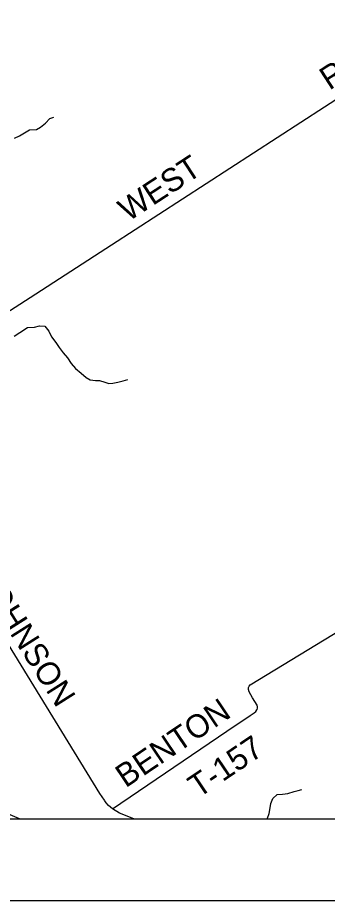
# Model space of a CAD drawing. Extents: x 0 to 34, y 0 to 22.
# Drawn here: x 3.909 to 4.289, y 14 to 15.083 of the extents above; entities that cross this region are included whole.
import ezdxf

# ---------------------------------------------------------------- set-up
doc = ezdxf.new("R2010")
doc.units = 0
for name, color, linetype in [('GM_X_Corporation', 7, 'Continuous'), ('GM_X_County_Road', 7, 'Continuous'), ('GM_X_County_Road_Text', 7, 'Continuous'), ('GM_X_Minor_River', 7, 'Continuous'), ('GM_X_Rail_Line', 7, 'Continuous'), ('GM_X_Township_Road', 7, 'Continuous'), ('GM_X_Township_Road_Text', 7, 'Continuous'), ('SH_Data', 7, 'Continuous')]:
    doc.layers.add(name, color=color, linetype=linetype)

msp = doc.modelspace()

# ---------------------------------------------------------------- linework, layer by layer
at = {"layer": 'GM_X_Corporation'}
msp.add_lwpolyline([(2.8939, 16.1007), (2.8444, 15.5792), (2.791, 14.9974), (2.7825, 14.9057), (2.7612, 14.682), (2.7426, 14.4873), (2.7141, 14.1915), (2.7124, 14.1801), (2.7115, 14.1703), (2.7095, 14.1457), (2.7076, 14.1245), (2.7052, 14.1), (8.9, 14.1)], dxfattribs=at)
at = {"layer": 'GM_X_County_Road'}
for points in [[(3.7386, 14.6201), (3.9241, 14.7398), (4.024, 14.8043), (4.3438, 15.011), (4.352, 15.0164), (4.3575, 15.0207), (4.3594, 15.0236), (4.361, 15.0279), (4.3615, 15.0333), (4.361, 15.0387), (4.3591, 15.0433), (4.3522, 15.0538), (4.306, 15.1259), (4.6205, 15.2578), (4.8635, 15.2772), (5.1173, 15.2978), (5.2791, 15.3117)], [(4.0153, 14.1229), (4.0098, 14.1309), (3.793, 14.4839), (3.787, 14.4942), (3.7866, 14.4951)], [(4.0517, 14.1), (4.0338, 14.1069), (4.0252, 14.1121), (4.0206, 14.1162), (4.0174, 14.1198), (4.0158, 14.1221), (4.0153, 14.1229)]]:
    msp.add_lwpolyline(points, dxfattribs=at)
at = {"layer": 'GM_X_Minor_River'}
for points in [[(3.9236, 14.9455), (3.9318, 14.9459), (3.9369, 14.9487), (3.943, 14.9534), (3.9485, 14.9591), (3.9532, 14.9609)], [(3.9113, 14.938), (3.9236, 14.9455)], [(3.9049, 14.9352), (3.9113, 14.938)], [(3.9044, 14.6923), (3.9114, 14.6967), (3.9209, 14.7029)], [(3.9209, 14.7029), (3.9296, 14.7034), (3.9358, 14.7047), (3.9424, 14.7043), (3.947, 14.6982), (3.9505, 14.6912), (3.9556, 14.6845), (3.9599, 14.6782), (3.9648, 14.6717), (3.9699, 14.6657), (3.9744, 14.6588), (3.98, 14.6527), (3.987, 14.6466), (3.993, 14.6414), (3.998, 14.6388), (4.0044, 14.6378), (4.0093, 14.6376), (4.0159, 14.6356), (4.0208, 14.6343), (4.0256, 14.6344), (4.0318, 14.6357), (4.0383, 14.6374), (4.0442, 14.6391)], [(4.2154, 14.1), (4.2156, 14.1008), (4.2175, 14.1065), (4.2183, 14.1112), (4.2197, 14.1188), (4.2222, 14.1251), (4.2273, 14.13), (4.2341, 14.1301), (4.2404, 14.1312), (4.2482, 14.1334), (4.2531, 14.1347), (4.2578, 14.1359)]]:
    msp.add_lwpolyline(points, dxfattribs=at)
at = {"layer": 'GM_X_Rail_Line'}
msp.add_lwpolyline([(3.9113, 14.1), (3.8881, 14.1099), (3.8378, 14.1355), (3.8275, 14.1422), (3.8141, 14.1496), (3.8062, 14.1546), (3.7684, 14.1699)], dxfattribs=at)
at = {"layer": 'GM_X_Township_Road'}
for points in [[(4.1925, 14.261), (4.1931, 14.2627), (4.1944, 14.2644), (4.376, 14.3749), (4.4383, 14.4126), (4.4441, 14.4167), (4.4479, 14.4199), (4.4539, 14.4257), (4.4598, 14.4305), (4.4631, 14.4331), (4.467, 14.4355), (4.6752, 14.566)], [(4.2028, 14.234), (4.2034, 14.2358), (4.2034, 14.2376), (4.203, 14.2393), (4.1974, 14.2486), (4.1932, 14.256), (4.1924, 14.2587), (4.1923, 14.2604), (4.1925, 14.261)], [(4.0252, 14.1121), (4.1656, 14.2076), (4.1945, 14.2267), (4.1991, 14.2299), (4.2013, 14.2318), (4.2027, 14.2336), (4.2028, 14.234)]]:
    msp.add_lwpolyline(points, dxfattribs=at)
at = {"layer": 'SH_Data'}
for p, q in [((2.1, 14.1), (8.9, 14.1)), ((2, 14), (9, 14))]:
    msp.add_line(p, q, dxfattribs=at)

# ---------------------------------------------------------------- texts
at = {"layer": 'GM_X_County_Road_Text'}
for s, rotation, p in [('RD', 33.0029, (4.2917, 14.9933)), ('WEST', 33.0849, (4.0446, 14.8321)), ('JOHNSON', 302.3092, (3.8581, 14.392))]:
    msp.add_text(s, height=0.02841, rotation=rotation, dxfattribs=at).set_placement(p)
at = {"layer": 'GM_X_Township_Road_Text'}
for s, rotation, p in [('BENTON', 34.0193, (4.0415, 14.1374)), ('T-157', 34.0773, (4.1308, 14.1248))]:
    msp.add_text(s, height=0.02841, rotation=rotation, dxfattribs=at).set_placement(p)

doc.saveas('drawing.dxf')
